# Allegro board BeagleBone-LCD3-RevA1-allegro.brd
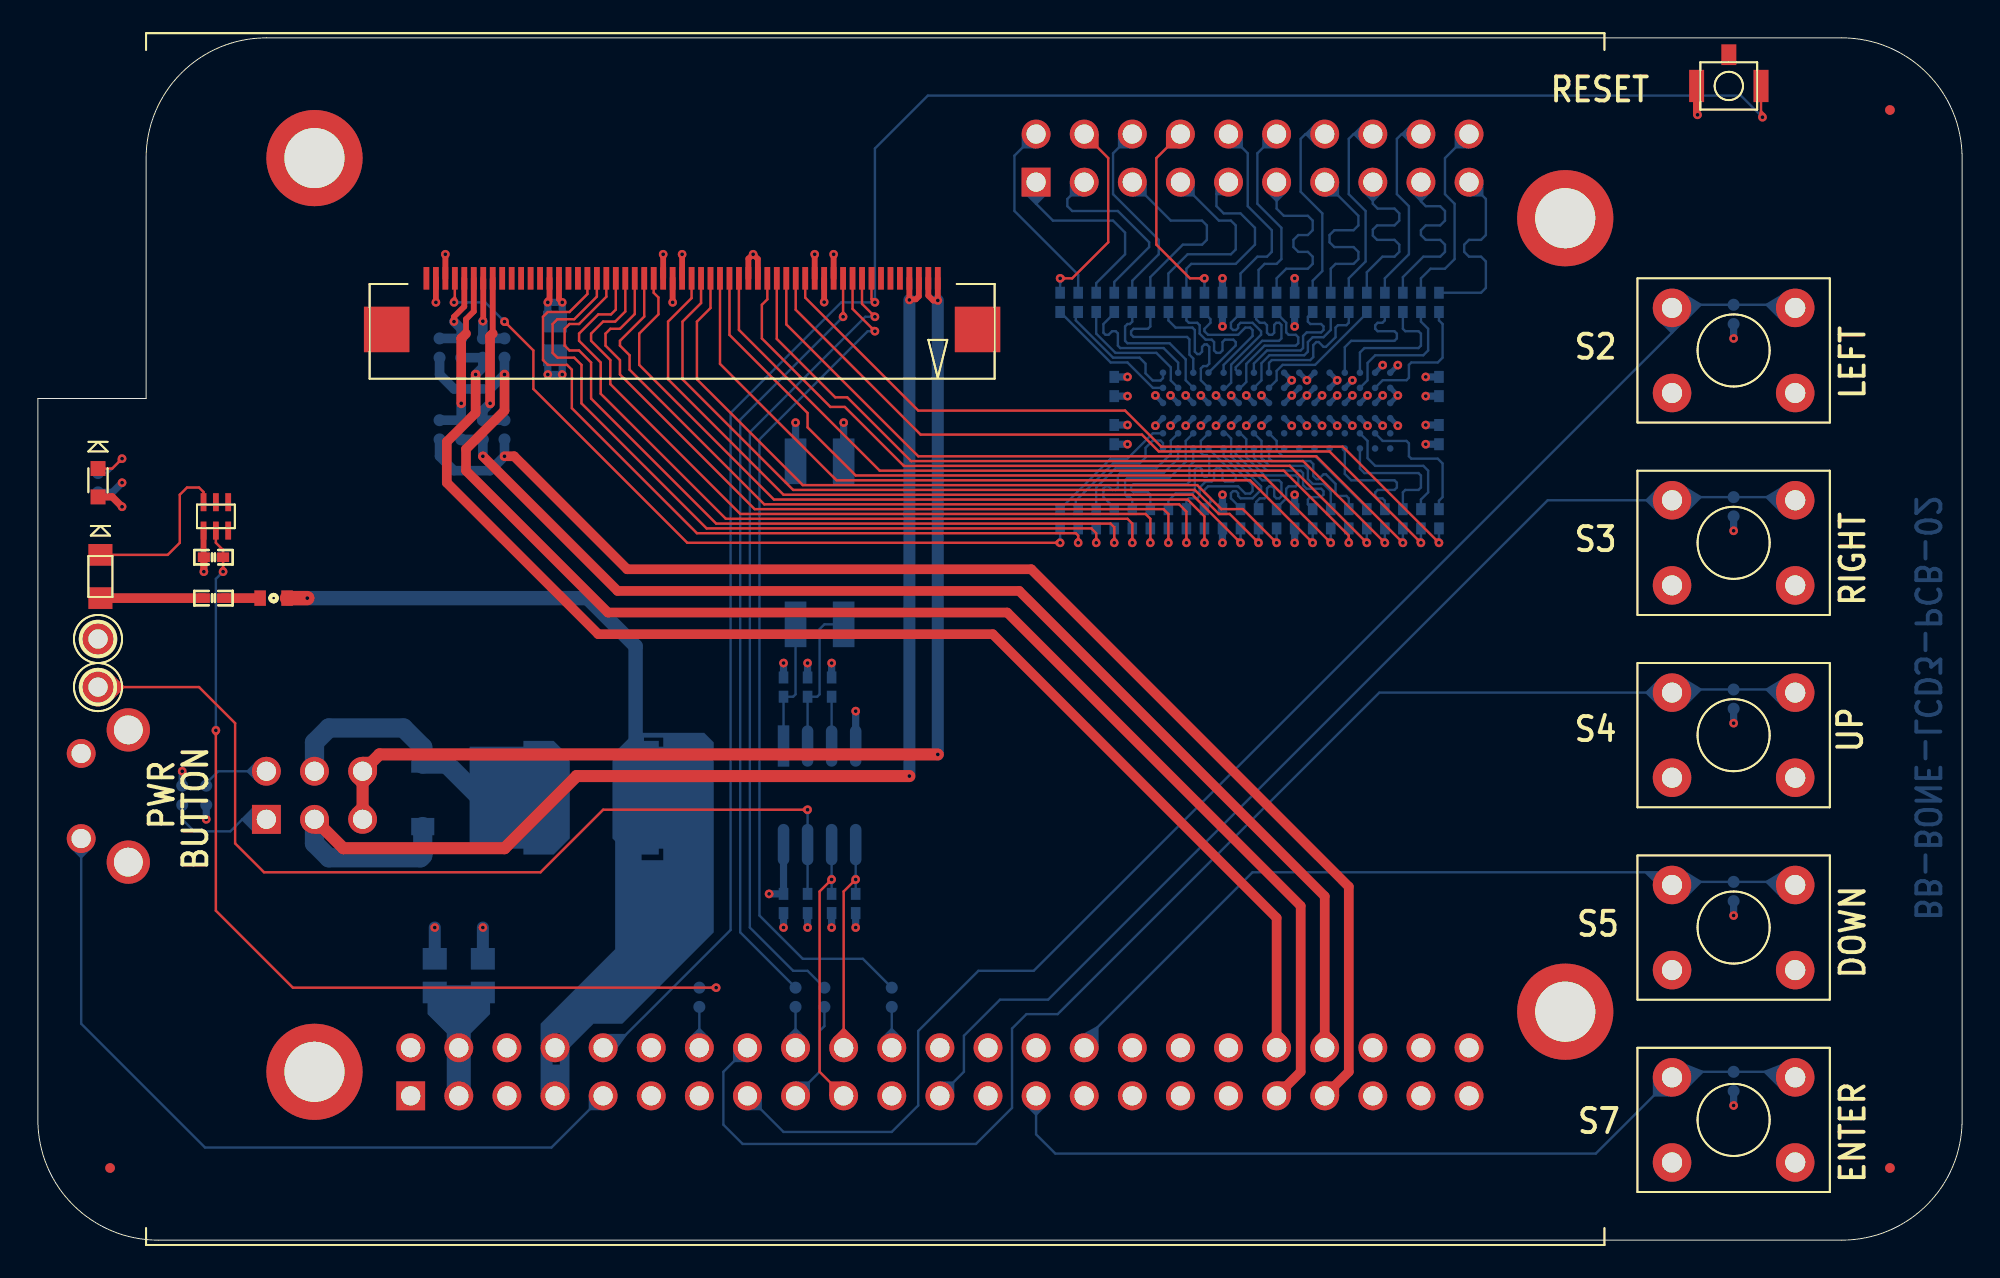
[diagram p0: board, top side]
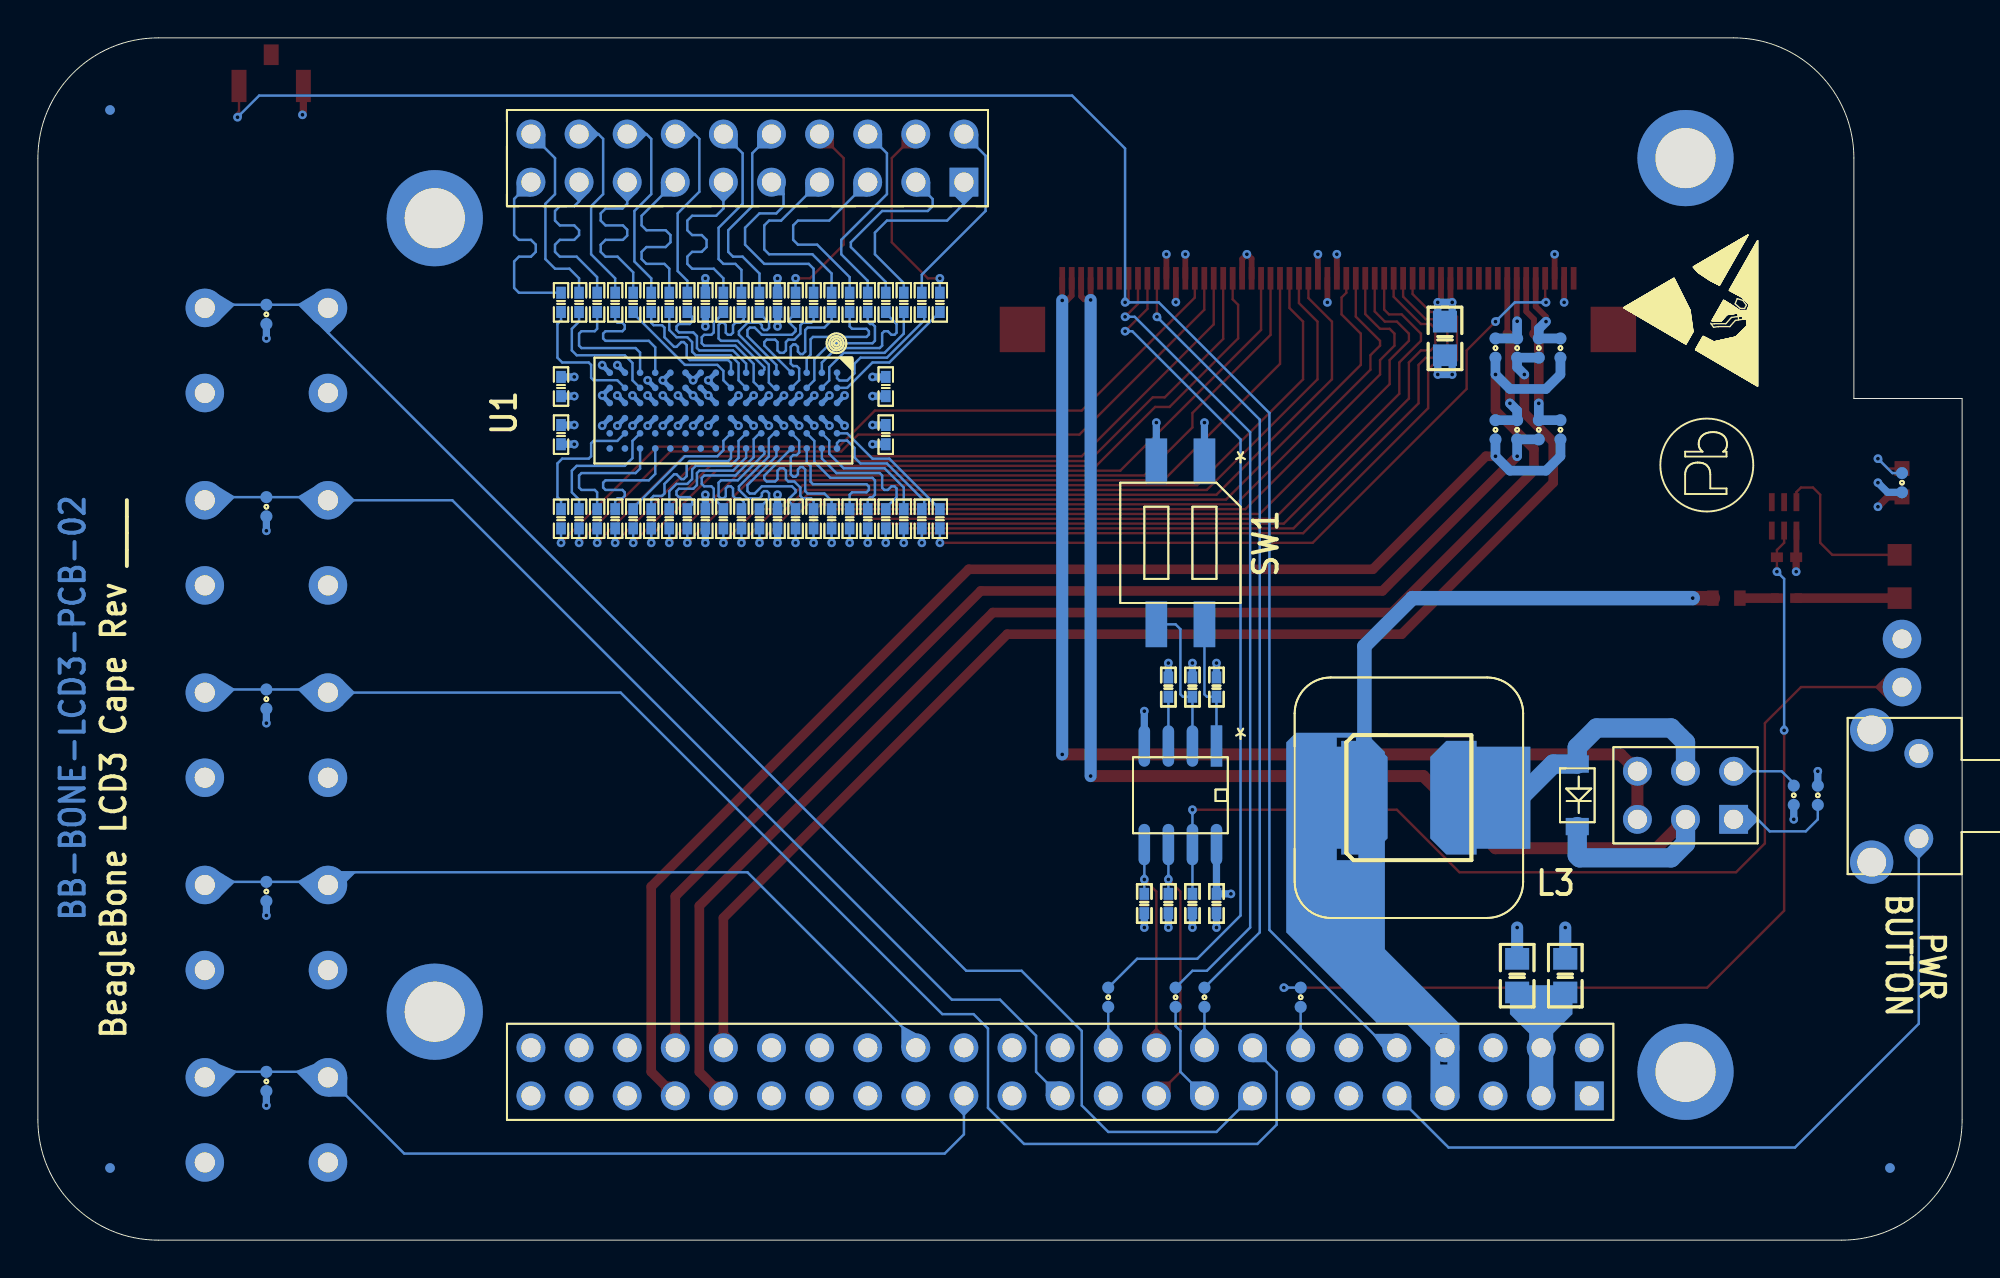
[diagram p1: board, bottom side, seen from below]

Outline 101.6 x 63.5 mm; copper layers: TOP, LYR2-GND, LYR3-PWR, BOTTOM. Coordinates in mm from the lower left corner of the outline.
Outline path: 0,44.45 5.71,44.45 5.71,57.15 arc(7.57,61.64) 12.06,63.5 95.25,63.5 arc(99.74,61.64) 101.6,57.15 101.6,6.35 arc(99.74,1.86) 95.25,0 6.35,0 arc(1.86,1.86) 0,6.35 0,44.45

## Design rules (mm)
net group CLK: nets BPCLK

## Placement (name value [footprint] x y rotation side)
C1  10uF,10V  [805]  20.95 13.97 270 bottom
C2  10uF,10V  [805]  23.5 13.97 270 bottom
C5  0.1uF  [402]  56.83 45.09 270 bottom
C6  0.1uF  [402]  56.83 42.55 270 bottom
C7  0.1uF  [402]  62.55 49.53 270 bottom
C8  0.1uF  [402]  62.55 38.1 270 bottom
C9  0.1uF  [402]  66.36 49.53 270 bottom
C10  0.1uF  [402]  73.98 45.09 270 bottom
C11  0.1uF  [402]  66.36 38.1 270 bottom
C12  0.1uF  [402]  73.98 42.55 270 bottom
C13  10uF,10V  [805]  27.3 47.62 90 bottom
C41  0.1uF  [402]  39.37 17.78 90 bottom
D3  LTST-C190GKT  [LED2-31SQ]  3.17 40.01 270 top
D4  MBRX140-TP  [SOD-123]  20.32 23.5 270 bottom
D5  598-8170-107F  [LED0805-1]  3.3 35.05 270 top
FB8  MMZ1608R301A  [IND603-24X32]  12.45 33.91 0 top
J1  CONN PCB 10x2-S  [HDR2X10]  52.7 55.88 0 top
J2  MALE HEADER 2x23  [HDR2X23]  19.68 7.62 0 top
J3  HEADER 3X2  [HDR2X3]  12.06 22.23 90 top
J4  62684-5521N0ALF  [CONN55_P5MM_5X33SMD]  34.02 50.8 90 top
L3  18uH, DNI  [IND390SMD_472SQ]  29.21 23.37 180 bottom
L4  10uH  [VLC6045T-100M]  29.21 23.37 180 bottom
NOREF  -  []  5.71 -0.25 0 top
NOREF#2  -  []  0 0 0 top
NOREF#3  -  [unnamed#2]  80.64 12.06 0 top
NOREF#4  -  []  0 0 0 top
NOREF#5  -  []  -236.09 -286.95 0 top
NOREF#6  -  [unnamed#2]  80.64 53.98 0 top
NOREF#7  -  []  5.71 63.5 0 top
NOREF#8  -  []  0 0 90 top
NOREF#9  -  [unnamed#2]  97.79 59.69 0 top
NOREF#10  -  []  99.94 61.44 0 top
NOREF#11  -  []  101.6 12.7 0 top
NOREF#12  -  [unnamed#2]  3.81 3.81 0 top
NOREF#13  -  [unnamed#2]  14.61 57.15 0 top
NOREF#14  -  []  14.61 8.89 0 top
NOREF#15  -  [unnamed#2]  97.79 3.81 0 top
NOREF#16  -  []  20.32 26.67 0 top
NOREF#17  -  []  80.64 53.98 0 top
NOREF#18  -  []  0 44.45 0 top
NOREF#19  -  []  -233.55 -285.68 0 top
NOREF#20  -  []  80.64 53.98 0 top
NOREF#21  -  []  5.71 44.45 0 top
NOREF#22  -  []  0 0 0 top
NOREF#23  -  []  14.61 57.15 0 top
NOREF#24  -  [unnamed#2]  14.61 8.89 0 top
NOREF#25  -  []  14.61 8.89 0 top
NOREF#26  -  [unnamed#2]  3.81 3.81 180 bottom
NOREF#27  -  [unnamed#2]  97.79 3.81 180 bottom
NOREF#28  -  [unnamed#2]  97.79 59.69 180 bottom
Q1  DMC56404  [SMINI6-F3-B]  9.4 38.23 180 top
R1  33,402  [402]  53.98 49.53 270 bottom
R2  10,402  [402]  53.98 38.1 270 bottom
R3  10,402  [402]  54.93 38.1 270 bottom
R4  33,402  [402]  55.88 49.53 270 bottom
R5  10,402  [402]  55.88 38.1 270 bottom
R6  10,402  [402]  56.83 38.1 270 bottom
R7  33,402  [402]  57.78 49.53 270 bottom
R8  33,402  [402]  58.74 49.53 270 bottom
R9  10,402  [402]  58.74 38.1 270 bottom
R10  33,402  [402]  59.69 49.53 270 bottom
R11  10,402  [402]  59.69 38.1 270 bottom
R12  33,402  [402]  60.64 49.53 270 bottom
R13  33,402  [402]  63.5 49.53 270 bottom
R14  33,402  [402]  54.93 49.53 270 bottom
R15  33,402  [402]  56.83 49.53 270 bottom
R16  10,402  [402]  57.78 38.1 270 bottom
R17  10,402  [402]  60.64 38.1 270 bottom
R18  10,402  [402]  63.5 38.1 270 bottom
R19  33,402  [402]  61.59 49.53 270 bottom
R20  10,402  [402]  61.59 38.1 270 bottom
R21  33,402  [402]  65.41 49.53 270 bottom
R22  10,402  [402]  65.41 38.1 270 bottom
R23  33,402  [402]  64.45 49.53 270 bottom
R24  10,402  [402]  64.45 38.1 270 bottom
R25  33,402  [402]  68.26 49.53 270 bottom
R26  10,402  [402]  68.26 38.1 270 bottom
R27  33,402  [402]  67.31 49.53 270 bottom
R28  10,402  [402]  67.31 38.1 270 bottom
R29  33,402  [402]  70.17 49.53 270 bottom
R30  10,402  [402]  70.17 38.1 270 bottom
R31  33,402  [402]  69.22 49.53 270 bottom
R32  10,402  [402]  69.22 38.1 270 bottom
R33  33,402  [402]  71.12 49.53 270 bottom
R34  10,402  [402]  71.12 38.1 270 bottom
R35  33,402  [402]  73.03 49.53 270 bottom
R36  10,402  [402]  73.03 38.1 270 bottom
R37  33,402  [402]  72.07 49.53 270 bottom
R38  10,402  [402]  72.07 38.1 270 bottom
R39  33,402  [402]  73.98 49.53 270 bottom
R40  10,402  [402]  73.98 38.1 270 bottom
R63  330  [R402-25]  3.17 40.01 90 bottom
R65  5.6K,5%  [402]  41.91 17.78 90 bottom
R66  5.6K,5%  [402]  43.18 17.78 90 bottom
R67  4.75K  [402]  41.91 29.21 270 bottom
R68  4.75K  [402]  40.64 29.21 270 bottom
R69  4.75K  [402]  39.37 29.21 270 bottom
R70  100K  [R402-25]  8.89 23.5 90 bottom
R71  100K  [R402-25]  7.62 23.5 270 bottom
R72  4.75K  [402]  40.64 17.78 90 bottom
R74  0  [C402-25]  23.5 47.12 270 bottom
R75  0, DNI  [C402-25]  22.35 47.12 270 bottom
R76  0  [C402-25]  21.21 47.12 270 bottom
R77  0, DNI  [C402-25]  24.64 47.12 270 bottom
R78  0  [C402-25]  21.21 42.8 270 bottom
R79  0, DNI  [C402-25]  24.64 42.8 270 bottom
R80  10K  [SM-7351-RES-0402]  89.53 28.57 270 bottom
R81  10K  [SM-7351-RES-0402]  89.53 18.41 270 bottom
R82  10K  [SM-7351-RES-0402]  89.53 38.73 270 bottom
R83  10K  [SM-7351-RES-0402]  89.53 48.9 270 bottom
R84  0  [C402-25]  23.5 42.8 270 bottom
R85  0, DNI  [C402-25]  22.35 42.8 270 bottom
R86  0, DNI  [C402-25]  41.53 12.83 90 bottom
R87  0, DNI  [C402-25]  40.01 12.83 270 bottom
R88  0, DNI  [C402-25]  45.09 12.83 270 bottom
R89  10K  [SM-7351-RES-0402]  89.53 8.38 270 bottom
R90  0  [C402-25]  34.92 12.83 270 bottom
R119  470,5%  [402]  9.27 33.91 180 top
R121  100K,1%  [402]  9.27 36.07 180 top
S1  B3U-1100  [SW3_4X2P5]  89.28 60.96 180 top
S2  B3F-1000  [SWRST4_177X256LS-1]  89.53 46.99 0 top
S3  B3F-1000  [SWRST4_177X256LS-1]  89.53 36.83 0 top
S4  B3F-1000  [SWRST4_177X256LS-1]  89.53 26.67 0 top
S5  B3F-1000  [SWRST4_177X256LS-1]  89.53 16.51 0 top
S6  B3F-3100  [SW4-B3F-315X]  2.29 21.21 90 bottom
S7  B3F-1000  [SWRST4_177X256LS-1]  89.53 6.35 0 top
SW1  SW DIP-2  [SWDIP4_100-339SMD]  41.27 36.83 270 bottom
TP1  T POINT A  [TP1-8040]  3.17 29.21 0 top
TP2  T POINT A  [TP1-8040]  3.17 31.75 0 top
U1  74avc32t245  [BGA96-ZKE]  65.41 43.81 90 bottom
U4  CAT24C256W  [SOIC_8]  41.27 23.5 0 bottom

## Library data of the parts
C1 C2 C13 = CAP_10uF_Y5V_10V_10%_0805
C5-C12 C41 = CAP,0.1uF
D3 = LED_LTST-C150GKT
D4 = DIODE SCHOTTKY_0
D5 = LED_LTST-C150GKT: Tolerance: X; User Part Number: X
FB8 = FER_MMZ1608R301A: Tolerance: X; User Part Number: X
J1 = CONN PCB 10x2-S
J2 = HDR_46_F_2_0.1_0.1
J3 = HEADER 3X2
J4 = CONN FLEX 54_0
L3 L4 = INDUCTOR
Q1 = RN1907
R1-R40 = RES_33_0402
R63 R70 R71 = RES_330_0402
R65 R66 R119 = RES_470_1/10W_5%_0402
R67-R69 R72 = RES_4.7K_0402
R74-R79 R84-R88 R90 = RES_33: User Part Number: USERPART#; Tolerance: 1%; tolerance: 1%
R80-R83 R89 = 10KOhmResistor1/16W0402
R121 = RES_100K_1/16W_1%_0402
S1 = SW_DP_MOM
S2-S7 = SW_KT11P2JM_4
SW1 = SW DIP-2
TP1 TP2 = T POINT A
U1 = 74avc8t245_0
U4 = CAT24C256W

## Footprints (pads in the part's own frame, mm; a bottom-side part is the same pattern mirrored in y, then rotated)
402
  rect 0.635x0.508 smd: 1(-0.508,0) 2(0.508,0)
805
  rect 1.143x1.27 smd: 1(-0.889,0) 2(0.889,0)
BGA96-ZKE
  round 0.351 smd: A1(1.999,-5.999) A2(1.199,-5.999) A3(0.399,-5.999) A4(-0.401,-5.999) A5(-1.201,-5.999) A6(-2.002,-5.999) B1(1.999,-5.199) B2(1.199,-5.199) B3(0.399,-5.199) B4(-0.401,-5.199) B5(-1.201,-5.199) B6(-2.002,-5.199) C1(1.999,-4.399) C2(1.199,-4.399) C3(0.399,-4.399) C4(-0.401,-4.399) C5(-1.201,-4.399) C6(-2.002,-4.399) D1(1.999,-3.599) D2(1.199,-3.599) D3(0.399,-3.599) D4(-0.401,-3.599) D5(-1.201,-3.599) D6(-2.002,-3.599) E1(1.999,-2.799) E2(1.199,-2.799) E3(0.399,-2.799) E4(-0.401,-2.799) E5(-1.201,-2.799) E6(-2.002,-2.799) F1(1.999,-1.999) F2(1.199,-1.999) F3(0.399,-1.999) F4(-0.401,-1.999) F5(-1.201,-1.999) F6(-2.002,-1.999) G1(1.999,-1.199) G2(1.199,-1.199) G3(0.399,-1.199) G4(-0.401,-1.199) G5(-1.201,-1.199) G6(-2.002,-1.199) H1(1.999,-0.401) H2(1.199,-0.401) H3(0.399,-0.401) H4(-0.401,-0.401) H5(-1.201,-0.401) H6(-2.002,-0.401) J1(1.999,0.399) J2(1.199,0.399) J3(0.399,0.399) J4(-0.401,0.399) J5(-1.201,0.399) J6(-2.002,0.399) K1(1.999,1.199) K2(1.199,1.199) K3(0.399,1.199) K4(-0.401,1.199) K5(-1.201,1.199) K6(-2.002,1.199) L1(1.999,1.999) L2(1.199,1.999) L3(0.399,1.999) L4(-0.401,1.999) L5(-1.201,1.999) L6(-2.002,1.999) M1(1.999,2.799) M2(1.199,2.799) M3(0.399,2.799) M4(-0.401,2.799) M5(-1.201,2.799) M6(-2.002,2.799) N1(1.999,3.599) N2(1.199,3.599) N3(0.399,3.599) N4(-0.401,3.599) N5(-1.201,3.599) N6(-2.002,3.599) P1(1.999,4.399) P2(1.199,4.399) P3(0.399,4.399) P4(-0.401,4.399) P5(-1.201,4.399) P6(-2.002,4.399) R1(1.999,5.199) R2(1.199,5.199) R3(0.399,5.199) R4(-0.401,5.199) R5(-1.201,5.199) R6(-2.002,5.199) T1(1.999,5.999) T2(1.199,5.999) T3(0.399,5.999) T4(-0.401,5.999) T5(-1.201,5.999) T6(-2.002,5.999)
C402-25
  round 0.635 smd: 1(-0.508,0) 2(0.508,0)
CONN55_P5MM_5X33SMD
  rect 2.4x2.4 smd: (-2.7,15.6) (-2.7,-15.6)
  rect 1.194x0.305 smd: 1(0,-13.5) 2(0,-13) 3(0,-12.5) 4(0,-12) 5(0,-11.5) 6(0,-11) 7(0,-10.5) 8(0,-10) 9(0,-9.5) 10(0,-9) 11(0,-8.5) 12(0,-8) 13(0,-7.5) 14(0,-7) 15(0,-6.5) 16(0,-6) 17(0,-5.5) 18(0,-5) 19(0,-4.5) 20(0,-4) 21(0,-3.5) 22(0,-3) 23(0,-2.5) 24(0,-2) 25(0,-1.5) 26(0,-1) 27(0,-0.5) 28(0,0) 29(0,0.5) 30(0,1) 31(0,1.5) 32(0,2) 33(0,2.5) 34(0,3) 35(0,3.5) 36(0,4) 37(0,4.5) 38(0,5) 39(0,5.5) 40(0,6) 41(0,6.5) 42(0,7) 43(0,7.5) 44(0,8) 45(0,8.5) 46(0,9) 47(0,9.5) 48(0,10) 49(0,10.5) 50(0,11) 51(0,11.5) 52(0,12) 53(0,12.5) 54(0,13) 55(0,13.5)
HDR2X3
  rect 1.524x1.524 hole 1.016: 1(0,0)
  round 1.524 hole 1.016: 2(2.54,0) 3(0,-2.54) 4(2.54,-2.54) 5(0,-5.08) 6(2.54,-5.08)
HDR2X10
  rect 1.524x1.524 hole 1.016: 1(0,0)
  round 1.524 hole 1.016: 2(0,2.54) 3(2.54,0) 4(2.54,2.54) 5(5.08,0) 6(5.08,2.54) 7(7.62,0) 8(7.62,2.54) 9(10.16,0) 10(10.16,2.54) 11(12.7,0) 12(12.7,2.54) 13(15.24,0) 14(15.24,2.54) 15(17.78,0) 16(17.78,2.54) 17(20.32,0) 18(20.32,2.54) 19(22.86,0) 20(22.86,2.54)
HDR2X23
  rect 1.524x1.524 hole 1.016: 1(0,0)
  round 1.524 hole 1.016: 2(0,2.54) 3(2.54,0) 4(2.54,2.54) 5(5.08,0) 6(5.08,2.54) 7(7.62,0) 8(7.62,2.54) 9(10.16,0) 10(10.16,2.54) 11(12.7,0) 12(12.7,2.54) 13(15.24,0) 14(15.24,2.54) 15(17.78,0) 16(17.78,2.54) 17(20.32,0) 18(20.32,2.54) 19(22.86,0) 20(22.86,2.54) 21(25.4,0) 22(25.4,2.54) 23(27.94,0) 24(27.94,2.54) 25(30.48,0) 26(30.48,2.54) 27(33.02,0) 28(33.02,2.54) 29(35.56,0) 30(35.56,2.54) 31(38.1,0) 32(38.1,2.54) 33(40.64,0) 34(40.64,2.54) 35(43.18,0) 36(43.18,2.54) 37(45.72,0) 38(45.72,2.54) 39(48.26,0) 40(48.26,2.54) 41(50.8,0) 42(50.8,2.54) 43(53.34,0) 44(53.34,2.54) 45(55.88,0) 46(55.88,2.54)
IND390SMD_472SQ
  rect 2.921x5.385 smd: 1(-4.953,0) 2(4.953,0)
IND603-24X32
  rect 0.61x0.813 smd: 1(-0.711,0) 2(0.711,0)
LED2-31SQ
  rect 0.787x0.787 smd: 1(-0.749,0) 2(0.749,0)
LED0805-1
  rect 1.143x1.27 smd: 1(-1.143,0) 2(1.143,0)
R402-25
  round 0.635 smd: 1(-0.508,0) 2(0.508,0)
SM-7351-RES-0402
  round 0.635 smd: 1(-0.508,0) 2(0.508,0)
SMINI6-F3-B
  rect 0.305x0.95 smd: 1(0.65,0.75) 2(0,0.75) 3(-0.65,0.75) 4(-0.65,-0.75) 5(0,-0.75) 6(0.65,-0.75)
SOD-123
  rect 0.914x1.219 smd: 1(1.651,0) 2(-1.651,0)
SOIC_8
  rect 0.61x2.184 smd: 1(-1.905,-2.603)
  oval 0.61x2.184 smd: 2(-0.635,-2.603) 3(0.635,-2.603) 4(1.905,-2.603) 5(1.905,2.603) 6(0.635,2.603) 7(-0.635,2.603) 8(-1.905,2.603)
SW3_4X2P5
  rect 0.787x1.702 smd: 1(-1.7,0) 2(1.7,0)
  rect 0.787x1.092 smd: 3(0,-1.65)
SW4-B3F-315X
  round 1.524 hole 1.016: 1(0,0) 2(4.496,0)
  round 2.286 hole 1.524: 3(-1.245,2.489) 4(5.74,2.489)
SWDIP4_100-339SMD
  rect 2.413x1.143 smd: 1(-4.305,1.27) 2(-4.305,-1.27) 3(4.305,-1.27) 4(4.305,1.27)
SWRST4_177X256LS-1
  round 2.032 hole 1.067: 1(-3.251,-2.248) 2(3.251,-2.248) 3(-3.251,2.248) 4(3.251,2.248)
TP1-8040
  round 2.032 hole 1.016: 1(0,0)
unnamed#2
  round 5.08 hole 3.175: 1(0,0)
VLC6045T-100M
  custom 0.613x0.613 smd: 1(-2.35,0) 2(2.35,0)

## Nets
DGND: C1.1 C2.1 C5.1 C6.2 C7.1 C8.2 C9.1 C10.1 C11.2 C12.2 C13.1 C41.1 J2.1 J2.2(26) J2.43(22) J2.44(47) J2.45(23) J2.46(48) J4.12 J4.13 J4.14 J4.20 J4.21 J4.28 J4.29 J4.30 J4.53 J4.54 Q1.1(4) R63.1 R70.1 R71.1 R121.2 S1.2(A2) S2.1(A1) S2.2(A2) S3.1(A1) S3.2(A2) S4.1(A1) S4.2(A2) S5.1(A1) S5.2(A2) S6.2(A2) S6.3(B1) S6.4(B2) S7.1(A1) S7.2(A2) SW1.1(A1) SW1.2(A2) TP2.1(TP) U1.A3(1DIR) U1.A4(1OE*) U1.B3(GND1) U1.B4(GND16) U1.D3(GND2) U1.D4(GND15) U1.E3(GND3) U1.E4(GND14) U1.G3(GND4) U1.G4(GND13) U1.H3(2DIR) U1.H4(2OE*) U1.J1(3B2) U1.J2(3B1) U1.J3(3DIR) U1.J4(3OE*) U1.K1(3B4) U1.K2(3B3) U1.K3(GND5) U1.K4(GND12) U1.L1(3B6) U1.L2(3B5) U1.M1(3B8) U1.M2(3B7) U1.M3(GND6) U1.M4(GND11) U1.N2(4B1) U1.N3(GND7) U1.N4(GND10) U1.R1(4B6) U1.R3(GND8) U1.R4(GND9) U1.T1(4B8) U1.T2(4B7) U1.T3(4DIR) U1.T4(4OE*) U4.4(VSS)
VDD_3V3: C1.2 C2.2 C5.2 C6.1 C7.2 C8.1 C9.2 C10.2 C11.1 C12.1 C13.2 C41.2 D3.2(A) J2.3(2) J2.4(27) J4.41 J4.42 R65.1 R66.1 R67.1 R68.1 R69.1 R72.1 R80.2(P2) R81.2(P2) R82.2(P2) R83.2(P2) R89.2(P2) U1.C3(VCCB1) U1.C4(VCCA1) U1.F3(VCCB2) U1.F4(VCCA2) U1.L3(VCCB3) U1.L4(VCCA3) U1.P3(VCCB4) U1.P4(VCCA4) U4.8(VCC)
AIN0: J2.39(20) R78.2(P2) R79.2(P2)
AIN1: J2.40(45) R84.2(P2) R85.2(P2)
AIN2: J2.37(19) R76.2(P2) R77.2(P2)
AIN3: J2.38(44) R74.2(P2) R75.2(P2)
B_D0: R40.1 U1.R5(4A5)
B_D1: R36.1 U1.P5(4A3)
B_D2: R38.1 U1.P6(4A4)
B_D3: R34.1 U1.N6(4A2)
B_D4: R30.1 U1.H5(2A7)
B_D5: R32.1 U1.H6(2A8)
B_D6: R26.1 U1.G5(2A5)
B_D7: R28.1 U1.G6(2A6)
B_D8: R22.1 U1.F5(2A3)
B_D9: R24.1 U1.F6(2A4)
B_D10: R18.1 U1.E5(2A1)
B_D11: R20.1 U1.E6(2A2)
B_D12: R17.1 U1.D6(1A8)
B_D13: R11.1 U1.D5(1A7)
B_D14: R9.1 U1.C6(1A6)
B_D15: R16.1 U1.C5(1A5)
B_HSYNC: R6.1 U1.B6(1A4)
B_LCDEN: R2.1 U1.A5(1A1)
B_PCLK: R3.1 U1.A6(1A2)
B_VSYNC: R5.1 U1.B5(1A3)
BBLU0: J4.15 R40.2
BBLU1: J4.16 R36.2
BBLU2: J4.17 R38.2
BBLU3: J4.18 R34.2
BBLU4: J4.19 R30.2
BEN: J4.52 R2.2
BGRN0: J4.22 R32.2
BGRN1: J4.23 R26.2
BGRN2: J4.24 R28.2
BGRN3: J4.25 R22.2
BGRN4: J4.26 R24.2
BGRN5: J4.27 R18.2
BHSYNC: J4.36 R6.2
BL+: D4.1(CATHODE) J3.3 J4.3 J4.4
BL-: J3.5 J3.6 J4.1 J4.2
BL_IN: D4.2(ANODE) J3.4 L3.2 L4.2
BL_ISET1: J3.2 R70.2
BL_ISET2: J3.1 R71.2
BLU0: R39.2 U1.R2(4B5)
BLU1: R35.2 U1.P2(4B3)
BLU2: R37.2 U1.P1(4B4)
BLU3: R33.2 U1.N1(4B2)
BLU4: R29.2 U1.H2(2B7)
BOTTOM: J4.49 R74.1(P1) R77.1(P1)
BPCLK: J4.38 R3.2
BRED0: J4.31 R20.2
BRED1: J4.32 R17.2
BRED2: J4.33 R11.2
BRED3: J4.34 R9.2
BRED4: J4.35 R16.2
BVSYNC: J4.37 R5.2
GPIO1_16: J2.15(8) R83.1(P1) S2.3(B1) S2.4(B2)
GPIO1_17: J2.23(12) R82.1(P1) S3.3(B1) S3.4(B2)
GPIO1_19: J2.16(33) R80.1(P1) S4.3(B1) S4.4(B2)
GPIO3_16: J2.30(40) R81.1(P1) S5.3(B1) S5.4(B2)
GPIO3_19: J2.27(14) R89.1(P1) S7.3(B1) S7.4(B2)
GRN0: R31.2 U1.H1(2B8)
GRN1: R25.2 U1.G2(2B5)
GRN2: R27.2 U1.G1(2B6)
GRN3: R21.2 U1.F2(2B3)
GRN4: R23.2 U1.F1(2B4)
GRN5: R13.2 U1.E2(2B1)
I2C2_SCL: J2.19(10) R65.2 U4.6(SCL)
I2C2_SDA: J2.20(35) R66.2 U4.5(SDA)
LCD_DATA0: J1.19(10) R39.1
LCD_DATA1: J1.20 R35.1
LCD_DATA2: J1.17(9) R37.1
LCD_DATA3: J1.18(19) R33.1
LCD_DATA4: J1.15(8) R29.1
LCD_DATA5: J1.16(18) R31.1
LCD_DATA6: J1.13(7) R25.1
LCD_DATA7: J1.14(17) R27.1
LCD_DATA8: J1.11(6) R21.1
LCD_DATA9: J1.12(16) R23.1
LCD_DATA10: J1.10(15) R13.1
LCD_DATA11: J1.8(14) R19.1
LCD_DATA12: J1.9(5) R12.1
LCD_DATA13: J1.7(4) R10.1
LCD_DATA14: J1.5(3) R8.1
LCD_DATA15: J1.6(13) R7.1
LCD_EN: J1.4(12) R1.1
LCD_HSYNC: J1.3(2) R15.1
LCD_PCLK: J1.2(11) R14.1
LCD_VSYNC: J1.1 R4.1
LCDEN: R1.2 U1.A2(1B1)
LCDHSYNC: R15.2 U1.B1(1B4)
LCDPCLK: R14.2 U1.A1(1B2)
LCDVSYNC: R4.2 U1.B2(1B3)
LEDAA: D5.2(A) R119.2
LEDAC: D5.1(C) Q1.6(3)
LEFT: J4.50 R78.1(P1) R85.1(P1)
PWR_BUT: J2.9(5) S6.1(A1)
PWRLED_R: D3.1(C) R63.2
RED0: R19.2 U1.E1(2B2)
RED1: R12.2 U1.D1(1B8)
RED2: R10.2 U1.D2(1B7)
RED3: R8.2 U1.C1(1B6)
RED4: R7.2 U1.C2(1B5)
RESET: J2.10(30) J4.8 S1.1(A1)
RIGHT: J4.48 R79.1(P1) R84.1(P1)
SPI_CLK: J4.10 R88.1(P1)
SPI_CS: J4.9 R86.2(P2)
SPI_MOSI: J4.11 R87.1(P1)
SW1_A0: R69.2 SW1.4(B1) U4.1(A0)
SW1_A1: R68.2 SW1.3(B2) U4.2(A1)
SW1_A3: R67.2 U4.3(A2)
SYS_5V: FB8.2 J2.7(4) J2.8(29) L3.1 L4.1
TOP: J4.51 R75.1(P1) R76.1(P1)
USER_LED1: Q1.2(5) R90.1(P1) R121.1
N17082289: J2.17(9) R86.1(P1)
N17082325: J2.22(36) R88.2(P2)
N17093100: J2.18(34) R87.2(P2)
N17102435: R72.2 TP1.1(TP) U4.7(WP)
N17103152: FB8.1 R119.1
N17103612: J2.14(32) R90.2(P2)

Pads without a net: J2 5 6 11 12 13 21 24 25 26 28 29 31 32 33 34 35 36 41 42; J4 5 6 7 39 40 43 44 45 46 47 55; NOREF#3 1; NOREF#6 1; NOREF#9 1; NOREF#12 1; NOREF#13 1; NOREF#15 1; NOREF#24 1; NOREF#26 1; NOREF#27 1; NOREF#28 1; Q1 3 4 5; S1 3; U1 J5 J6 K5 K6 L5 L6 M5 M6 N5 R6 T5 T6

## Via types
v1: diameter 0.457, hole 0.203, TOP to BOTTOM, 140 vias

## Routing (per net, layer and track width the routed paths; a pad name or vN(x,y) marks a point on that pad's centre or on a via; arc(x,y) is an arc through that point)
DGND: length 159.4
  TOP w0.305: J4.14 v1(41.02,52.07) ; J4.21 37.52,51.84 v1(37.77,52.07) 38.02,51.82 J4.20 ; Q1.1 8.75,36.08 ; J4.28 v1(34.02,52.07) ; J4.12 v1(42.02,52.07) ; J4.29 v1(33.52,49.53) ; J4.13 v1(41.52,49.54) ; J4.30 v1(33.02,52.07) ; J4.54 v1(21.02,49.53) ; J4.53 v1(21.52,52.07)
  TOP w0.381: S1.2 87.58,59.49 v1(87.63,59.44) ; 8.75,36.08 R121.2 v1(8.76,35.31)
  LYR2-GND w1.016: 72.26,6.85 J2.43 ; J2.43 73.79,8.39 ; J2.43 72.26,8.39 ; J2.43 73.79,6.85 ; 91.84,45.69 S2.2 ; S2.2 91.84,43.79 ; S2.2 93.74,45.69 ; S2.2 93.74,43.79 ; S4.2 93.74,23.47 ; S4.2 93.74,25.37 ; S4.2 91.84,23.47 ; S4.2 91.84,25.37 ; 91.84,35.53 S3.2 ; S3.2 91.84,33.63 ; S3.2 93.74,33.63 ; S3.2 93.74,35.53 ; J2.44 73.79,9.39 ; J2.44 72.26,9.39 ; J2.44 72.26,10.93 ; J2.44 73.79,10.93 ; 85.33,13.31 S5.1 ; S5.1 85.33,15.21 ; S5.1 87.23,15.21 ; S5.1 87.23,13.31 ; S7.1 87.23,5.05 ; S7.1 87.23,3.15 ; S7.1 85.33,3.15 ; S7.1 85.33,5.05 ; 91.84,13.31 S5.2 ; S5.2 93.74,15.21 ; S5.2 91.84,15.21 ; S5.2 93.74,13.31 ; 91.84,3.15 S7.2 ; S7.2 93.74,3.15 ; S7.2 93.74,5.05 ; S7.2 91.84,5.05 ; S6.2 3.06,26.47 ; S6.2 1.52,26.47 ; S6.2 1.52,24.94 ; S6.2 3.06,24.94 ; J2.45 76.33,8.39 ; J2.45 74.8,6.85 ; J2.45 76.33,6.85 ; J2.45 74.8,8.39 ; TP2.1 3.99,32.56 ; TP2.1 2.36,32.56 ; TP2.1 2.36,30.94 ; TP2.1 3.99,30.94 ; 74.8,9.39 J2.46 ; J2.46 76.33,9.39 ; J2.46 74.8,10.93 ; J2.46 76.33,10.93 ; 85.33,43.79 S2.1 ; S2.1 87.23,43.79 ; S2.1 85.33,45.69 ; S2.1 87.23,45.69 ; S3.1 87.23,33.63 ; S3.1 85.33,35.53 ; S3.1 85.33,33.63 ; S3.1 87.23,35.53 ; 18.92,10.93 J2.2 ; J2.2 20.45,10.93 ; J2.2 18.92,9.39 ; J2.2 20.45,9.39 ; S4.1 87.23,23.47 ; S4.1 85.33,25.37 ; S4.1 87.23,25.37 ; S4.1 85.33,23.47 ; J2.1 20.7,8.64 ; J2.1 18.67,6.6 ; J2.1 20.7,6.6 ; J2.1 18.67,8.64 ; S6.4 5.81,25.91 ; S6.4 3.74,25.91 ; S6.4 5.81,27.99 ; 3.74,21 S6.3 ; S6.3 5.81,21 ; S6.3 5.81,18.93 ; S6.3 3.74,18.93
  BOTTOM w0.254: U1.E4 62.6,43.41 v1(62.2,43.01) ; v1(69.41,43.01) 69.01,43.41 U1.N4 ; U1.B3 v1(59.8,44.62) ; U1.B4 60.2,43.41 v1(59.8,43.01) ; U1.J1 65.81,45.81 v1(66.21,45.42) U1.J2 ; U1.R3 v1(71.01,44.62) ; U1.R4 70.61,43.41 v1(71.01,43.01) ; v1(64.6,44.62) 65,44.22 U1.H3 ; U1.K1 66.61,45.81 v1(67.01,45.42) U1.L1 ; U1.T4 71.41,43.41 v1(71.81,43.01) ; U1.N2 v1(69.41,45.42) ; U1.R1 v1(71.01,46.22) ; U1.K2 v1(66.21,44.62) U1.J3 ; U1.T2 71.41,45.01 v1(71.81,44.62) U1.T3 ; U1.M2 v1(68.61,45.42) 68.21,45.81 U1.M1 ; U1.M4 68.21,43.41 v1(68.61,43.01) ; U1.N3 v1(69.41,44.62) ; U1.T1 v1(71.81,46.22) ; v1(59,43.01) 59.4,43.41 U1.A4 ; U1.M3 v1(68.61,44.62) ; U1.K3 v1(67.01,44.62) U1.L2 ; U1.K4 66.61,43.41 v1(67.01,43.01) ; U1.E3 v1(62.2,44.62) ; U1.G4 64.2,43.41 v1(63.8,43.01) ; U1.G3 v1(63.8,44.62) ; U1.A3 v1(59,44.62) ; U1.D3 v1(61.4,44.62) ; U1.J4 v1(66.21,43.01) ; U1.D4 61.8,43.41 v1(61.4,43.01) ; U1.H4 v1(64.6,43.01)
  BOTTOM w0.381: C12.2 v1(73.28,42.04) ; R70.1 v1(8.89,22.23) ; SW1.1 v1(40.01,43.18) ; C5.1 v1(57.53,45.59) ; R71.1 v1(7.62,24.77) ; v1(4.45,40.01) 3.94,39.5 R63.1 ; C6.2 v1(57.53,42.04) ; C41.1 v1(39.37,16.51) ; C7.1 v1(62.55,50.8) ; v1(66.36,36.83) C11.2 ; U4.4 v1(43.18,27.94) ; C10.1 v1(73.28,45.59) ; C8.2 v1(62.55,36.83) ; SW1.2 v1(42.55,43.18) ; C9.1 v1(66.36,50.8) ; v1(26.92,45.72) 26.92,46.35 C13.1 27.69,46.35 v1(27.69,45.72) v1(26.92,45.72)
  BOTTOM w0.635: C2.1 v1(23.5,16.51) ; C1.1 v1(20.95,16.51)
VDD_3V3: length 38.1
  TOP w0.305: v1(26.92,49.53) 27.02,49.62 J4.42 ; v1(27.69,49.53) 27.52,49.7 J4.41
  TOP w0.381: v1(4.45,38.73) 3.92,39.26 D3.2
  LYR3-PWR w1.016: J2.4 22.99,10.93 ; J2.4 21.46,9.39 ; J2.4 22.99,9.39 ; J2.4 21.46,10.93 ; 21.46,6.85 J2.3 ; J2.3 21.46,8.39 ; J2.3 22.99,8.39 ; J2.3 22.99,6.85
  BOTTOM w0.254: U1.L4 67.41,43.41 v1(67.81,43.01) ; v1(70.21,43.01) 69.81,43.41 U1.P4 ; v1(63,43.01) 63.4,43.41 U1.F4 ; v1(60.6,43.01) 61,43.41 U1.C4 ; U1.L3 v1(67.81,44.62) ; U1.F3 v1(63,44.62) ; U1.C3 v1(60.6,44.62) ; U1.P3 v1(70.21,44.62)
  BOTTOM w0.381: v1(38.61,18.29) C41.2 U4.8 ; R68.1 v1(40.64,30.48) ; R81.2 v1(89.53,17.14) ; C7.2 v1(62.55,48.26) ; R80.2 v1(89.53,27.3) ; R82.2 v1(89.53,37.47) ; 56.83,43.05 v1(57.53,43.05) ; R69.1 v1(39.37,30.48) ; R89.2 v1(89.53,7.11) ; 73.98,43.05 v1(73.28,43.05) ; R72.1 v1(40.64,16.51) ; R65.1 v1(41.91,16.51) ; C8.1 v1(62.55,39.37) ; C9.2 v1(66.36,48.26) ; R83.2 v1(89.53,47.62) ; R66.1 v1(43.18,16.51) ; R67.1 v1(41.91,30.48) ; C11.1 v1(66.36,39.37) ; C10.2 v1(73.28,44.58) ; C5.2 v1(57.53,44.58) ; v1(27.69,49.53) v1(26.92,49.53) 26.92,48.9 C13.2 27.69,48.9 v1(27.69,49.53)
AIN0: length 71.4
  TOP w0.508: v1(24.64,41.4) 25.15,41.4 31.11,35.43 52.45,35.43 69.22,18.67 69.22,8.89 J2.39
  BOTTOM w0.508: R78.2 21.21,41.4 21.97,40.64 23.88,40.64 v1(24.64,41.4) R79.2
AIN1: length 64.1
  TOP w0.508: J2.40 67.94,18.16 51.82,34.29 30.61,34.29 v1(23.5,41.4)
  BOTTOM w0.508: R85.2 R84.2 v1(23.5,41.4)
AIN2: length 75.9
  TOP w0.508: v1(24.64,45.72) 24.64,43.81 22.61,41.78 22.61,40.64 30.1,33.15 51.18,33.15 66.67,17.65 66.67,8.89 J2.37
  BOTTOM w0.508: R77.2 v1(24.64,45.72) 23.88,44.96 21.97,44.96 21.21,45.72 R76.2
AIN3: length 68.7
  TOP w0.508: v1(23.11,45.72) 23.11,43.69 21.59,42.16 21.59,40.01 29.59,32 50.42,32 65.41,17.02 J2.38
  BOTTOM w0.508: v1(23.11,45.72) 23.5,46.1 R74.2 R75.2
B_D0: length 7.1
  BOTTOM w0.127: U1.R5 71.01,42.21 72.26,42.21 72.39,42.09 72.39,41.4 72.52,41.27 73.91,41.27 74.17,41.02 74.17,39.24 73.98,39.05 R40.1
B_D1: length 7.1
  BOTTOM w0.127: R36.1 73.03,39.12 73.41,39.5 73.41,40.64 73.15,40.89 70.61,40.89 70.21,41.3 70.21,42.21 U1.P5
B_D2: length 7
  BOTTOM w0.127: U1.P6 69.8,40.75 70.04,40.51 72.9,40.51 73.03,40.39 73.03,39.75 72.9,39.62 72.2,39.62 72.07,39.5 R38.1
B_D3: length 7
  BOTTOM w0.127: R34.1 71.12,39.05 70.99,39.18 70.74,39.18 70.61,39.31 70.61,39.5 70.74,39.62 71.63,39.62 71.75,39.75 71.75,40.01 71.63,40.13 69.34,40.13 69,40.47 U1.N6
B_D4: length 7.2
  BOTTOM w0.127: R30.1 70.17,38.67 67.44,41.4 65.72,41.4 65.41,41.72 65.41,42.21 65.01,42.61 U1.H5
B_D5: length 7.1
  BOTTOM w0.127: U1.H6 65,41.3 65.15,41.15 67.18,41.15 67.34,40.99 67.34,40.35 67.5,40.2 67.63,40.2 67.88,40.45 68.01,40.45 68.52,39.94 68.52,39.43 68.64,39.31 69.09,39.31 69.22,39.18 R32.1
B_D6: length 7.1
  BOTTOM w0.127: R26.1 68.26,39.56 67.88,39.94 67.31,39.94 67.06,40.2 67.06,40.7 66.87,40.89 65.02,40.89 64.6,41.31 64.6,42.21 U1.G5
B_D7: length 7
  BOTTOM w0.127: R28.1 67.06,38.86 67.06,39.12 67.18,39.24 67.75,39.24 67.88,39.37 67.88,39.56 67.75,39.69 66.99,39.69 66.8,39.88 66.8,40.51 66.67,40.64 64.9,40.64 64.2,41.33 64.2,41.81 U1.G6
B_D8: length 7
  BOTTOM w0.127: U1.F5 63.49,42.61 63.8,42.3 63.8,41.35 64.77,40.39 66.42,40.39 66.55,40.26 66.55,39.94 66.42,39.81 66.04,39.81 65.91,39.69 65.91,39.18 65.41,38.67 R22.1
B_D9: length 7
  BOTTOM w0.127: R24.1 64.33,38.73 64.33,38.99 64.52,39.18 64.77,39.18 64.9,39.31 64.9,39.7 65.01,39.81 65.17,39.81 65.28,39.7 65.28,39.29 65.39,39.18 65.55,39.18 65.66,39.29 65.66,40.01 65.53,40.13 64.64,40.13 63.25,41.53 63.25,41.65 U1.F6
B_D10: length 7
  BOTTOM w0.127: R18.1 63.5,38.67 62.99,39.18 62.99,39.45 63.1,39.56 63.26,39.56 63.37,39.45 63.37,39.31 63.5,39.18 64.14,39.18 64.58,39.63 64.58,39.81 63,41.39 63,42.34 62.73,42.61 U1.E5
B_D11: length 7
  BOTTOM w0.127: R20.1 61.59,38.67 61.91,38.99 61.91,39.18 61.59,39.5 61.59,39.62 61.79,39.81 63.37,39.81 63.75,39.43 64.01,39.43 64.14,39.56 64.14,39.88 62.61,41.41 U1.E6
B_D12: length 7.1
  BOTTOM w0.127: R17.1 60.64,39.05 60.77,39.18 61.21,39.18 61.34,39.31 61.34,39.75 61.66,40.07 61.98,40.07 62.1,40.2 62.1,40.64 62.23,40.77 62.42,40.77 62.55,40.64 62.55,40.2 62.67,40.07 63.12,40.07 63.25,40.2 63.25,40.37 U1.D6
B_D13: length 7
  BOTTOM w0.127: U1.D5 61.4,42.21 61.4,41.59 61.53,41.47 61.72,41.47 61.85,41.34 61.85,40.45 61.72,40.32 61.59,40.32 61.47,40.45 61.47,40.7 61.34,40.83 61.21,40.83 61.09,40.7 61.09,39.56 60.96,39.43 60.07,39.43 59.69,39.05 R11.1
B_D14: length 7.1
  BOTTOM w0.127: R9.1 58.74,39.37 58.61,39.5 57.85,39.5 57.72,39.62 57.72,39.8 57.85,39.93 60.67,39.93 60.8,40.05 60.8,40.88 61,41.08 61,41.81 U1.C6
B_D15: length 7
  BOTTOM w0.127: R16.1 57.78,39.12 57.66,39.24 57.53,39.24 57.4,39.37 57.4,40.13 57.53,40.26 59.75,40.26 60.6,41.11 60.6,42.21 U1.C5
B_HSYNC: length 7
  BOTTOM w0.127: U1.B6 60.2,41.81 60.2,41.28 59.44,40.51 57.15,40.51 57.02,40.39 57.02,39.74 56.91,39.62 56.72,39.62 56.53,39.81 56.37,39.81 56.26,39.7 56.26,39.24 56.83,38.67 R6.1
B_LCDEN: length 7.1
  BOTTOM w0.127: R2.1 56.64,41.27 57.53,41.27 58.87,42.61 U1.A5
B_PCLK: length 7.1
  BOTTOM w0.127: R3.1 54.8,38.73 54.8,39.05 56.77,41.02 58.17,41.02 58.48,41.34 58.48,41.85 58.86,42.23 59.28,42.23 59.41,42.1 U1.A6
B_VSYNC: length 7.1
  BOTTOM w0.127: U1.B5 59.82,42.22 59.82,41.53 59.05,40.77 56.9,40.77 55.88,39.75 R5.1
BBLU0: length 40.6
  TOP w0.127: J4.15 40.52,49.78 46.48,43.81 57.4,43.81 59.31,41.91 68.9,41.91 v1(73.98,36.83)
  BOTTOM w0.127: R40.2 v1(73.98,36.83)
BBLU1: length 40.5
  TOP w0.127: v1(73.03,36.83) 68.2,41.66 59.18,41.66 58.29,42.55 46.61,42.55 40.02,49.14 J4.16
  BOTTOM w0.127: R36.2 v1(73.03,36.83)
BBLU2: length 40.5
  TOP w0.127: J4.17 39.52,48.37 46.48,41.4 67.5,41.4 v1(72.07,36.83)
  BOTTOM w0.127: R38.2 v1(72.07,36.83)
BBLU3: length 40.5
  TOP w0.127: v1(71.12,36.83) 66.8,41.15 46.1,41.15 42.74,44.51 42.1,44.51 39.02,47.6 J4.18
  BOTTOM w0.127: R34.2 v1(71.12,36.83)
BBLU4: length 40.5
  TOP w0.127: v1(70.17,36.83) 66.1,40.89 45.72,40.89 42.61,44.01 41.85,44.01 38.23,47.62 38.23,49.4 38.52,49.69 J4.19
  BOTTOM w0.127: R30.2 v1(70.17,36.83)
BEN: length 40.5
  TOP w0.127: v1(24.64,48.51) 26.16,46.99 26.16,44.96 34.29,36.83 v1(53.98,36.83) ; v1(21.97,49.53) 22.02,49.57 J4.52
  BOTTOM w0.127: v1(24.64,48.51) 23.62,49.53 v1(21.97,49.53) ; R2.2 v1(53.98,36.83)
BGRN0: length 40.6
  TOP w0.127: v1(69.22,36.83) 69.22,37.21 65.79,40.64 44.45,40.64 37.02,48.07 J4.22
  BOTTOM w0.127: R32.2 v1(69.22,36.83)
BGRN1: length 40.5
  TOP w0.127: v1(68.26,36.83) 64.71,40.39 43.18,40.39 40.64,42.93 40.64,43.69 36.52,47.81 J4.23
  BOTTOM w0.127: R26.2 v1(68.26,36.83)
BGRN2: length 40.5
  TOP w0.127: J4.24 36.02,46.28 42.16,40.13 64.01,40.13 v1(67.31,36.83)
  BOTTOM w0.127: R28.2 v1(67.31,36.83)
BGRN3: length 40.6
  TOP w0.127: v1(65.41,36.83) 63.63,38.61 62.48,38.61 61.21,39.88 40.39,39.88 34.8,45.47 34.8,48.51 35.52,49.23 J4.25
  BOTTOM w0.127: R22.2 v1(65.41,36.83)
BGRN4: length 40.5
  TOP w0.127: v1(64.45,36.83) 62.93,38.35 62.36,38.35 61.09,39.62 39.88,39.62 34.04,45.47 34.04,48.51 35.02,49.49 J4.26
  BOTTOM w0.127: R24.2 v1(64.45,36.83)
BGRN5: length 40.4
  TOP w0.127: v1(63.5,36.83) 60.96,39.37 39.37,39.37 33.27,45.47 33.27,48.51 34.52,49.76 J4.27
  BOTTOM w0.127: R18.2 v1(63.5,36.83)
BHSYNC: length 40.5
  TOP w0.127: v1(56.83,36.83) 56.83,37.66 56.64,37.85 35.81,37.85 29.21,44.45 29.21,46.35 28.57,46.99 28.07,46.99 27.81,47.24 27.81,48.13 28.07,48.39 28.57,48.39 30.02,49.83 J4.36
  BOTTOM w0.127: R6.2 v1(56.83,36.83)
BL+: length 70.3
  TOP w0.305: J4.3 46.52,49.85 46.35,49.69 46.02,49.69 ; 46.02,49.69 J4.4 ; 46.02,49.69 v1(46.02,49.66)
  TOP w0.635: J3.3 16.13,20.7 24.64,20.7 28.45,24.51 v1(46.02,24.51)
  BOTTOM w0.635: v1(46.02,49.66) v1(46.02,24.51)
  BOTTOM w1.016: D4.1 20.32,20.32 20.19,20.19 15.37,20.19 14.61,20.95 J3.3
BL-: length 59.9
  TOP w0.305: J4.1 47.52,49.64 ; 47.52,49.64 47.51,49.63 47.27,49.63 47.02,49.89 J4.2 ; 47.52,49.64 v1(47.52,49.63)
  TOP w0.635: J3.5 J3.6 18.03,25.65 v1(47.52,25.65)
  BOTTOM w0.635: v1(47.52,49.63) v1(47.52,25.65)
BL_IN: length 16.1
  BOTTOM w1.016: L4.2 L3.2 23.37,23.37 21.59,25.15 D4.2 20.32,26.04 19.3,27.05 15.37,27.05 14.61,26.29 J3.4
BL_ISET1: length 3.6
  BOTTOM w0.127: R70.2 8.89,24.13 9.53,24.77 J3.2
BL_ISET2: length 5.7
  BOTTOM w0.127: J3.1 10.79,22.23 10.16,21.59 8.26,21.59 7.62,22.23 R71.2
BLU0: length 7.1
  BOTTOM w0.127: R39.2 73.98,48.58 74.17,48.39 74.17,46.61 73.91,46.35 72.52,46.35 72.39,46.23 72.39,45.54 72.26,45.42 71.01,45.42 U1.R2
BLU1: length 7.1
  BOTTOM w0.127: R35.2 73.03,48.51 73.41,48.13 73.41,46.99 73.15,46.74 70.61,46.74 70.21,46.33 70.21,45.42 U1.P2
BLU2: length 7
  BOTTOM w0.127: U1.P1 69.8,46.88 70.04,47.12 72.9,47.12 73.03,47.24 73.03,47.88 72.9,48.01 72.2,48.01 72.07,48.13 R37.2
BLU3: length 7
  BOTTOM w0.127: U1.N1 69,47.16 69.34,47.5 71.63,47.5 71.75,47.62 71.75,47.88 71.63,48.01 70.74,48.01 70.61,48.13 70.61,48.32 70.74,48.45 70.99,48.45 71.12,48.58 R33.2
BLU4: length 7.2
  BOTTOM w0.127: R29.2 70.17,48.96 67.44,46.23 65.72,46.23 65.41,45.91 65.41,45.42 U1.H2
BOTTOM: length 4.3
  TOP w0.305: v1(23.5,48.53) 23.52,48.55 J4.49
  BOTTOM w0.508: R77.1 R74.1 v1(23.5,48.53)
BPCLK: length 40.4
  TOP w0.127: J4.38 29.02,49.97 28.07,49.02 26.92,49.02 26.67,48.77 26.67,46.48 26.92,46.23 27.94,46.23 28.19,45.97 28.19,43.94 34.8,37.34 54.8,37.34 54.93,37.21 v1(54.93,36.83)
  BOTTOM w0.127: R3.2 v1(54.93,36.83)
BRED0: length 40.4
  TOP w0.127: J4.31 32.52,50.04 32.77,49.79 32.77,48.9 31.75,47.88 31.75,46.23 38.86,39.12 60.71,39.12 61.59,38.23 v1(61.59,36.83)
  BOTTOM w0.127: R20.2 v1(61.59,36.83)
BRED1: length 40.5
  TOP w0.127: J4.32 32.02,48.78 30.73,47.5 30.73,47.24 31.24,46.74 31.24,45.97 38.35,38.86 60.26,38.86 60.64,38.48 v1(60.64,36.83)
  BOTTOM w0.127: R17.2 v1(60.64,36.83)
BRED2: length 40.6
  TOP w0.127: v1(59.69,36.83) 59.69,38.35 59.44,38.61 37.85,38.61 30.73,45.72 30.73,46.48 29.97,47.24 29.97,47.88 30.23,48.13 30.73,48.13 31.52,48.91 J4.33
  BOTTOM w0.127: R11.2 v1(59.69,36.83)
BRED3: length 40.6
  TOP w0.127: J4.34 31.02,49.05 30.48,48.51 29.84,48.51 29.21,47.88 29.21,47.5 30.23,46.48 30.23,45.21 37.08,38.35 58.48,38.35 58.74,38.1 v1(58.74,36.83)
  BOTTOM w0.127: R9.2 v1(58.74,36.83)
BRED4: length 40.5
  TOP w0.127: v1(57.78,36.83) 57.78,37.85 57.53,38.1 36.32,38.1 29.72,44.7 29.72,46.35 28.57,47.5 28.57,47.88 29.59,48.9 30.26,48.9 30.52,49.15 J4.35
  BOTTOM w0.127: R16.2 v1(57.78,36.83)
BVSYNC: length 40.5
  TOP w0.127: J4.37 29.52,49.84 28.32,48.64 27.43,48.64 27.18,48.39 27.18,46.86 27.43,46.61 28.32,46.61 28.7,46.23 28.7,44.2 35.31,37.59 55.63,37.59 55.88,37.34 v1(55.88,36.83)
  BOTTOM w0.127: R5.2 v1(55.88,36.83)
GPIO1_16: length 77.3
  BOTTOM w0.127: S2.4 92.62,49.4 R83.1 86.45,49.4 S2.3 86.28,47.93 52.58,14.22 49.66,14.22 46.48,11.05 46.48,7.11 45.09,5.71 39.37,5.71 J2.15
GPIO1_17: length 59.4
  BOTTOM w0.127: J2.23 48.9,8.89 48.9,10.79 50.8,12.7 53.34,12.7 79.72,39.08 S3.3 86.45,39.24 R82.1 92.62,39.24 S3.4
GPIO1_19: length 74.1
  BOTTOM w0.127: J2.16 36.2,8.89 36.2,6.1 37.21,5.08 49.53,5.08 51.44,6.99 51.44,11.18 52.2,11.94 53.85,11.94 70.83,28.92 S4.3 86.45,29.08 R80.1 92.62,29.08 S4.4
GPIO3_16: length 42
  BOTTOM w0.127: S5.4 92.62,18.92 R81.1 86.45,18.92 S5.3 85.61,19.43 64.14,19.43 55.24,10.54 55.24,10.16
GPIO3_19: length 44.4
  BOTTOM w0.127: S7.4 92.49,8.89 R89.1 86.58,8.89 S7.3 82.26,4.57 53.72,4.57 52.7,5.59 J2.27
GRN0: length 7.1
  BOTTOM w0.127: R31.2 69.22,48.45 69.09,48.32 68.64,48.32 68.52,48.2 68.52,47.69 68.01,47.18 67.88,47.18 67.63,47.43 67.5,47.43 67.34,47.28 67.34,46.64 67.18,46.48 65.15,46.48 65,46.33 U1.H1
GRN1: length 7.1
  BOTTOM w0.127: U1.G2 64.6,45.41 64.6,46.32 65.02,46.74 66.87,46.74 67.06,46.93 67.06,47.43 67.31,47.69 67.88,47.69 68.26,48.07 R25.2
GRN2: length 7
  BOTTOM w0.127: R27.2 67.06,48.77 67.06,48.51 67.18,48.39 67.75,48.39 67.88,48.26 67.88,48.07 67.75,47.94 66.99,47.94 66.8,47.75 66.8,47.12 66.67,46.99 64.9,46.99 64.2,46.3 64.2,45.82 U1.G1
GRN3: length 7
  BOTTOM w0.127: U1.F2 63.49,45.01 63.8,45.33 63.8,46.28 64.77,47.24 66.42,47.24 66.55,47.37 66.55,47.69 66.42,47.82 66.04,47.82 65.91,47.94 65.91,48.45 65.41,48.96 R21.2
GRN4: length 7
  BOTTOM w0.127: U1.F1 63.25,45.97 63.25,46.1 64.64,47.5 65.53,47.5 65.66,47.62 65.66,48.34 65.55,48.45 65.39,48.45 65.28,48.34 65.28,47.93 65.17,47.82 65.01,47.82 64.9,47.93 64.9,48.32 64.77,48.45 64.52,48.45 64.33,48.64 64.33,48.9 R23.2
GRN5: length 7
  BOTTOM w0.127: U1.E2 62.73,45.01 63,45.29 63,46.24 64.58,47.82 64.58,48 64.14,48.45 63.5,48.45 63.37,48.32 63.37,48.18 63.26,48.07 63.1,48.07 62.99,48.18 62.99,48.45 63.5,48.96 R13.2
I2C2_SCL: length 14.8
  TOP w0.127: J2.19 41.27,8.89 41.27,18.41 v1(41.91,19.05)
  BOTTOM w0.127: R65.2 v1(41.91,19.05) U4.6
I2C2_SDA: length 11.8
  TOP w0.127: J2.20 42.55,18.41 v1(43.18,19.05)
  BOTTOM w0.127: R66.2 v1(43.18,19.05) U4.5
LCD_DATA0: length 10.2
  BOTTOM w0.127: J1.19 76.45,54.99 76.45,53.09 76.2,52.83 75.56,52.83 75.31,52.58 75.31,52.2 75.56,51.94 76.2,51.94 76.45,51.69 76.45,50.29 76.2,50.04 R39.1
LCD_DATA1: length 10.3
  BOTTOM w0.127: R35.1 73.03,50.8 73.53,51.31 74.3,51.31 74.8,51.82 74.8,54.74 74.3,55.24 74.3,57.15 J1.20
LCD_DATA2: length 10.2
  BOTTOM w0.127: R37.1 72.07,50.86 73.15,51.94 74.04,51.94 74.3,52.2 74.3,52.58 74.04,52.83 73.28,52.83 73.03,53.09 73.03,53.34 73.28,53.59 74.04,53.59 74.3,53.85 74.3,54.36 74.04,54.61 73.28,54.61 73.03,54.86 J1.17
LCD_DATA3: length 10.3
  BOTTOM w0.127: J1.18 72.01,58.42 71.75,58.17 71.75,55.24 72.39,54.61 72.39,52.07 71.12,50.8 R33.1
LCD_DATA4: length 10.3
  BOTTOM w0.127: R29.1 70.17,51.12 70.99,51.94 71.63,51.94 71.88,52.2 71.88,52.58 71.63,52.83 70.71,52.83 70.48,53.06 70.48,53.37 70.71,53.59 71.63,53.59 71.88,53.85 71.88,54.23 71.63,54.48 70.74,54.48 70.48,54.74 J1.15
LCD_DATA5: length 10.2
  BOTTOM w0.127: R31.1 69.22,50.8 70.1,51.69 70.1,54.36 69.22,55.24 69.22,58.17 69.47,58.42 J1.16
LCD_DATA6: length 10.2
  BOTTOM w0.127: J1.13 69.72,54.1 69.72,53.59 69.47,53.34 68.45,53.34 68.2,53.09 68.2,52.7 68.45,52.45 69.47,52.45 69.72,52.2 69.72,51.82 69.47,51.56 68.52,51.56 68.26,51.31 R25.1
LCD_DATA7: length 10.2
  BOTTOM w0.127: J1.14 66.93,58.42 66.67,58.17 66.67,55.37 67.82,54.23 67.82,51.18 67.31,50.67 R27.1
LCD_DATA8: length 10.3
  BOTTOM w0.127: R21.1 65.41,50.8 65.91,51.31 67.06,51.31 67.31,51.56 67.31,51.94 67.06,52.2 66.55,52.2 66.29,52.45 66.29,52.83 66.55,53.09 67.06,53.09 67.31,53.34 67.31,53.85 67.06,54.1 65.79,54.1 65.41,54.48 J1.11
LCD_DATA9: length 10.2
  BOTTOM w0.127: J1.12 64.39,57.4 64.39,54.74 65.66,53.47 65.66,51.82 65.41,51.56 64.77,51.56 64.45,51.24 R23.1
LCD_DATA10: length 10.3
  BOTTOM w0.127: R13.1 63.5,51.05 64.39,51.94 64.9,51.94 65.15,52.2 65.15,53.34 63.88,54.61 63.88,57.4 J1.10
LCD_DATA11: length 10.4
  TOP w0.127: J1.8 59.05,57.15 59.05,52.58 60.83,50.8 v1(61.59,50.8)
  BOTTOM w0.127: R19.1 v1(61.59,50.8)
LCD_DATA12: length 10.3
  BOTTOM w0.127: J1.9 62.23,55.24 62.23,54.61 62.61,54.23 63.5,54.23 64.26,53.47 64.26,52.58 63.25,51.56 60.9,51.56 60.64,51.31 R12.1
LCD_DATA13: length 10.2
  BOTTOM w0.127: J1.7 62.36,53.85 62.99,53.85 63.25,53.59 63.25,52.32 62.99,52.07 60.71,52.07 59.69,51.05 R10.1
LCD_DATA14: length 10.3
  BOTTOM w0.127: R8.1 58.74,50.86 60.45,52.58 61.47,52.58 61.72,52.83 61.72,53.59 61.47,53.85 59.82,53.85 J1.5
LCD_DATA15: length 10.4
  BOTTOM w0.127: R7.1 57.78,50.67 59.18,52.07 59.18,52.83 56.77,55.24 56.77,57.4 J1.6
LCD_EN: length 10.3
  TOP w0.127: v1(53.98,50.8) 54.61,50.8 56.52,52.7 56.52,57.15 J1.4
  BOTTOM w0.127: R1.1 v1(53.98,50.8)
LCD_HSYNC: length 10.2
  BOTTOM w0.127: R15.1 56.83,50.61 58.67,52.45 58.67,52.7 57.02,54.36 54.61,54.36 54.36,54.61 54.36,54.99 J1.3
LCD_PCLK: length 10.2
  BOTTOM w0.127: R14.1 54.93,50.99 51.56,54.36 51.56,57.28 J1.2
LCD_VSYNC: length 10.3
  BOTTOM w0.127: J1.1 52.7,54.74 53.59,53.85 56.77,53.85 57.4,53.21 57.4,52.07 55.88,50.55 R4.1
LCDEN: length 7.1
  BOTTOM w0.127: U1.A2 58.87,45.01 57.53,46.35 56.64,46.35 R1.2
LCDHSYNC: length 7
  BOTTOM w0.127: R15.2 56.83,48.96 56.26,48.39 56.26,47.93 56.37,47.82 56.53,47.82 56.72,48.01 56.91,48.01 57.02,47.89 57.02,47.24 57.15,47.12 59.44,47.12 60.21,46.35 U1.B1
LCDPCLK: length 7.1
  BOTTOM w0.127: R14.2 54.8,48.9 54.8,48.58 56.77,46.61 58.17,46.61 58.48,46.29 58.48,45.78 58.86,45.4 59.28,45.4 59.41,45.53 U1.A1
LCDVSYNC: length 7.1
  BOTTOM w0.127: R4.2 55.88,47.88 56.9,46.86 59.05,46.86 59.82,46.1 59.82,45.4 U1.B2
LEDAA: length 5.5
  TOP w0.508: R119.2 D5.2
LEDAC: length 9
  TOP w0.127: D5.1 6.86,36.2 7.49,36.83 7.49,39.37 7.87,39.75 8.51,39.75 8.75,39.51 Q1.6
LEFT: length 8.9
  TOP w0.305: J4.50 23.02,49.05 22.61,48.64 22.61,47.88
  TOP w0.508: 22.61,47.88 22.35,47.62 v1(22.35,44.2)
  BOTTOM w0.508: R78.1 R85.1 v1(22.35,44.2)
PWR_BUT: length 41.2
  BOTTOM w0.127: J2.9 27.11,4.89 8.83,4.89 2.29,11.43 S6.1
PWRLED_R: length 3.1
  TOP w0.127: D3.1 3.92,40.75 v1(4.45,41.27)
  BOTTOM w0.127: v1(4.45,41.27) 3.68,40.51 3.17,40.51
RED0: length 7
  BOTTOM w0.127: U1.E1 62.61,46.22 64.14,47.75 64.14,48.07 64.01,48.2 63.75,48.2 63.37,47.82 61.79,47.82 61.59,48.01 61.59,48.13 61.91,48.45 61.91,48.64 61.59,48.96 R19.2
RED1: length 7.1
  BOTTOM w0.127: R12.2 60.64,48.58 60.77,48.45 61.21,48.45 61.34,48.32 61.34,47.88 61.66,47.56 61.98,47.56 62.1,47.43 62.1,46.99 62.23,46.86 62.42,46.86 62.55,46.99 62.55,47.43 62.67,47.56 63.12,47.56 63.25,47.43 63.25,47.25 U1.D1
RED2: length 7
  BOTTOM w0.127: R10.2 59.69,48.58 60.07,48.2 60.96,48.2 61.09,48.07 61.09,46.93 61.21,46.8 61.34,46.8 61.47,46.93 61.47,47.18 61.59,47.31 61.72,47.31 61.85,47.18 61.85,46.29 61.72,46.16 61.53,46.16 61.4,46.04 61.4,45.42 U1.D2
RED3: length 7.1
  BOTTOM w0.127: R8.2 58.74,48.26 58.61,48.13 57.85,48.13 57.72,48.01 57.72,47.83 57.85,47.7 60.67,47.7 60.8,47.58 60.8,46.77 61.01,46.56 U1.C1
RED4: length 7
  BOTTOM w0.127: U1.C2 60.6,45.42 60.6,46.52 59.75,47.37 57.53,47.37 57.4,47.5 57.4,48.26 57.53,48.39 57.66,48.39 57.78,48.51 R7.2
RESET: length 106.3
  TOP w0.127: J4.8 44.02,49.71 v1(44.2,49.53) ; v1(91.06,59.31) 90.98,59.39 S1.1
  BOTTOM w0.127: v1(91.06,59.31) 89.92,60.45 46.99,60.45 44.2,57.66 v1(44.2,49.53) 42.42,49.53 36.58,43.69 36.58,16.38 30.35,10.16 J2.10
RIGHT: length 8.9
  TOP w0.305: 24.02,47.88 J4.48
  TOP w0.508: 24.02,47.88 23.88,47.74 v1(23.88,44.2)
  BOTTOM w0.508: v1(23.88,44.2) 23.5,43.81 R84.1 R79.1
SPI_CLK: length 45.5
  TOP w0.127: v1(44.2,48.01) 43.02,49.19 J4.10
  BOTTOM w0.127: v1(44.2,48.01) 43.81,48.01 38.1,42.29 38.1,17.14 40.39,14.86 43.56,14.86 R88.1
SPI_CS: length 42.9
  TOP w0.127: v1(44.2,48.77) 43.52,49.45 J4.9
  BOTTOM w0.127: R86.2 40.64,14.22 39.88,14.22 37.59,16.51 37.59,42.67 43.69,48.77 v1(44.2,48.77)
SPI_MOSI: length 40.9
  TOP w0.127: J4.11 v1(42.52,48.77)
  BOTTOM w0.127: v1(42.52,48.77) 37.08,43.34 37.08,16.26 R87.1
SW1_A0: length 7
  BOTTOM w0.127: U4.1 R69.2 39.88,28.7 40.01,28.83 SW1.4
SW1_A1: length 8.1
  BOTTOM w0.127: SW1.3 41.53,32.52 41.27,32.27 41.27,28.83 41.15,28.7 R68.2 U4.2
SW1_A3: length 2.6
  BOTTOM w0.127: U4.3 R67.2
SYS_5V: length 27.5
  TOP w0.762: FB8.2 v1(14.22,33.91)
  BOTTOM w0.762: L4.1 31.56,31.37 29.02,33.91 v1(14.22,33.91)
TOP: length 4.7
  TOP w0.305: v1(21.97,48.51) 21.97,48.77 22.52,49.31 J4.51
  BOTTOM w0.508: v1(21.97,48.51) 22.35,48.13 R75.1 R76.1
USER_LED1: length 49.4
  TOP w0.127: v1(9.4,26.92) 9.4,17.4 13.46,13.34 v1(35.81,13.34) ; Q1.2 9.4,36.83 9.78,36.45 R121.1 v1(9.78,35.31)
  BOTTOM w0.127: v1(9.78,35.31) 9.4,34.92 v1(9.4,26.92) ; R90.1 v1(35.81,13.34)
N17082289: length 5.3
  BOTTOM w0.127: J2.17 41.27,8.89 41.27,11.05 41.53,11.3 41.53,12.32
N17082325: length 2.2
  BOTTOM w0.127: 45.09,12.32 J2.22
N17093100: length 2.2
  BOTTOM w0.127: 40.01,12.32 J2.18
N17102435: length 51
  TOP w0.127: v1(40.64,22.73) 29.84,22.73 26.54,19.43 11.94,19.43 10.41,20.95 10.41,27.3 8.51,29.21 TP1.1
  BOTTOM w0.127: v1(40.64,22.73) U4.7 R72.2
N17103152: length 2
  TOP w0.508: R119.1 FB8.1
N17103612: length 2.2
  BOTTOM w0.127: 34.92,12.32 J2.14

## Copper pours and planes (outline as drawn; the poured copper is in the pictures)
DGND on LYR2-GND: 6.35,1.27 2.76,2.76 1.27,6.35 1.27,43.18 6.99,43.18 6.99,57.15 8.47,60.74 12.06,62.23 95.25,62.23 98.84,60.74 100.33,57.15 100.33,6.35 98.84,2.76 95.25,1.27
VDD_3V3 on BOTTOM (solid shape): 23.88,13.21 23.88,11.94 22.86,10.92 22.86,7.62 22.61,7.37 21.84,7.37 21.59,7.62 21.59,10.92 20.57,11.94 20.57,13.21 20.83,13.46 23.62,13.46
VDD_3V3 on LYR3-PWR: 6.35,1.27 2.76,2.76 1.27,6.35 1.27,43.18 6.99,43.18 6.99,57.15 8.47,60.74 12.06,62.23 95.25,62.23 98.84,60.74 100.33,57.15 100.33,6.35 98.84,2.76 95.25,1.27
GPIO1_16 on BOTTOM (solid shape): 87.83,49.46 87.86,49.41 87.84,49.36 87,48.52 86.27,49.24 86.99,49.97
GPIO1_16 on BOTTOM (solid shape): 92.8,49.24 92.07,48.52 91.23,49.36 91.21,49.41 91.24,49.46 92.08,49.97
GPIO1_17 on BOTTOM (solid shape): 86.3,39.08 85.57,38.36 84.89,39.03 84.87,39.08 84.89,39.12 85.57,39.8
GPIO1_17 on BOTTOM (solid shape): 87.83,39.3 87.86,39.25 87.84,39.2 87,38.36 86.27,39.08 86.99,39.81
GPIO1_17 on BOTTOM (solid shape): 92.8,39.08 92.07,38.36 91.23,39.2 91.21,39.25 91.24,39.3 92.08,39.81
GPIO1_19 on BOTTOM (solid shape): 86.3,28.92 85.57,28.2 84.89,28.87 84.87,28.92 84.89,28.96 85.57,29.64
GPIO1_19 on BOTTOM (solid shape): 87.83,29.14 87.86,29.09 87.84,29.04 87,28.2 86.27,28.92 86.99,29.65
GPIO1_19 on BOTTOM (solid shape): 92.8,28.92 92.07,28.2 91.23,29.04 91.21,29.09 91.24,29.14 92.08,29.65
GPIO3_16 on BOTTOM (solid shape): 86.3,18.75 85.57,18.66 84.84,19.39 84.89,19.43 85.61,19.43
GPIO3_16 on BOTTOM (solid shape): 87.83,18.98 87.86,18.93 87.84,18.88 87,18.04 86.27,18.76 86.99,19.49
GPIO3_16 on BOTTOM (solid shape): 92.8,18.76 92.07,18.04 91.23,18.88 91.21,18.93 91.24,18.98 92.08,19.49
GPIO3_19 on BOTTOM (solid shape): 86.28,7.58 85.33,7.58 85.29,7.6 85.27,7.65 85.27,8.6 86.29,8.61
GPIO3_19 on BOTTOM (solid shape): 87.92,8.95 87.95,8.9 87.94,8.85 87,7.91 86.27,8.6 86.98,9.32
GPIO3_19 on BOTTOM (solid shape): 92.8,8.6 92.07,7.91 91.13,8.85 91.12,8.9 91.15,8.95 92.09,9.32
SYS_5V on BOTTOM (solid shape): 35.69,26.29 35.69,16.26 30.86,11.43 29.34,11.43 28.07,10.16 28.07,7.37 27.69,6.99 27.05,6.99 26.54,7.49 26.54,9.27 27.56,9.27 27.56,9.65 27.18,9.65 27.18,9.27 26.54,9.27 26.54,10.54 27.56,10.54 27.56,10.92 27.18,10.92 27.18,10.54 26.54,10.54 26.54,11.43 30.48,15.37 30.48,20.07 33.02,20.07 33.02,21.08 31.88,21.08 31.88,20.07 30.48,20.07 30.48,25.53 33.02,25.53 33.02,26.54 32,26.54 32,25.53 30.48,25.53 30.48,25.78 31.5,26.8 35.18,26.8
N17102435 on TOP (solid shape): 4.57,29.25 4.59,29.21 4.57,29.17 3.89,28.49 3.16,29.21 3.89,29.93

Small or netless copper shapes (teardrops, artwork), in the pictures only: 62 on TOP, 159 on BOTTOM

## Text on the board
BOTTOM: BB-BONE-LCD3-PCB-02 | LAYER 4 | SOLDER
Board Geometry/Soldermask Bottom: SMS
Ref Des/Silkscreen Bottom: PWR | BUTTON | BeagleBone LCD3 Cape Rev ____ | BSLK
User.Comments: LCD LITE 3.5
TOP: LAYER 1 | COMPONENT
Board Geometry/Soldermask Top: SMC
Ref Des/Silkscreen Top: RESET | PWR | BUTTON | UP | LEFT | RIGHT | DOWN | ENTER | TSLK
LYR2-GND: LAYER 2 | GROUND
LYR3-PWR: LAYER 3 | POWER
DIMENSION: 4 PLS.
USER_PART_NUM_TOP: TSLKC
USER_PART_NUM_BOTTOM: BSLKC
DISPLAY_BOTTOM: SPS
DISPLAY_TOP: SPC
DEVICE_TYPE_BOTTOM: DATE | DESIGN ENGR | PROJECT ENGR | ENGR MGR | NEXT ASSEMBLY | APPROVED | CHECKED | DRAFTING | ENGR | NONE | 1 OF 1 | 10.  LAYER 1 AND 4 SHALL BE IMPEDENCE CONTROLLED, FOR 5 MIL LINES TO BE,50 OHMS. | 1   TOTAL BOARD THICKNESS SHALL BE .062 +/- 10% INCHES. | 5.  APPLY LPI SILKSCREEN OR EQUIVALENT PER THE ARTWORK COLOR:BLACK. | 4.  SOLDERMASK ON BOTH SIDES OF THE BOARD SHALL BE S.M.O.B.C., LPI, COLOR WHITE. | 3.  MINIMUM TRACE AND SPACE SHALL BE .005 OF AN INCH. | 2.  COPPER PLATED SURFACE CONDUCTORS SHALL BE THE EQUIVALENT OF 1 OZ. COPPER | 8.  FINISHED BOARD SHALL BE FREE OF BURRS ON EDGES. | 7.  DRC'S MUST BE RAN ON THE GERBERS BEFORE BUILDING BOARDS UNLESS PRIOR | 6.  PLATED THRU HOLE SIZE TOLERANCES SHALL BE +/- .003 INCH. | 9.  SURFACE FINISH SHALL BE IMMERSION SILVER. | AFTER PLATING.  PLANE LAYERS SHALL BE 1 OZ. COPPER.  AVERAGE COPPER ON | THE WALL OF THE PLATED HOLE SHALL BE PER IPC CLASS 2. | ALL MATERIAL SHALL BE NEMA GRADE FR-4 OR EQUIVALENT. (Tg>=170 DEG. C) | APPROVAL IS GIVEN IN WRITING. | UNPLATED THRU HOLE SIZE TOLERANCES SHALL BE +/- .002 INCH. | LAYER 1 | LAYER 2 | NOTES: UNLESS OTHERWISE SPECIFIED
User.9: DATE | DESIGN ENGR | PROJECT ENGR | ENGR MGR | NEXT ASSEMBLY | APPROVED | CHECKED | DRAFTING | ENGR | 1 OF 1
User.10: NONE
User.12: 1. All board outlines shall be .020 in width. | 2. All other lines shall be .012 in width. | 3. Note and misc. text shall be text block 10. | 4. View and description text shall be text block 16. | 5. Make sure that there is not any double dimensioning, | 6. Check all notes to make sure that they apply and are correct. | 7. Make sure that layer stack-up is correct. | label (REF) dim when needed.
User.13: USER LEDS | 2 | 3 | 0 | 1 | RESET | 10 | 9 | 21 | 15 | 7 | 48 | 18 | 16 | 33 | 32 | V | A | R | 46 | 45 | PWR | 22 | 28 | 14 | 8 | 64 | 49 | 17 | AM335x | USB Host | USB | Ethernet | microSD Card
User.16: FIGURE | SIZE | 8.0 | 40.0 | 42.0 | 60.0 | 125.0 | ALL UNITS ARE IN MILS | DRILL CHART: TOP to BOTTOM | TOLERANCE | +3.0/-3.0 | PLATED | QTY | 140 | 2 | 74 | 20 | 4
